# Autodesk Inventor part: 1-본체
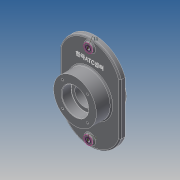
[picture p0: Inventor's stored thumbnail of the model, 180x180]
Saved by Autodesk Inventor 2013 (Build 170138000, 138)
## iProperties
Created: 2015-02
Part Number: 1-본체
Material: 일반
Document SubType Name: Modeling
Designer: kb543-18
Density: 1 g/cm^3
Mass: 603.771 g
Surface Area: 900.498 cm^2
Volume: 603.771 cm^3
Author: kb543-18
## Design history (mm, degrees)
sketch "스케치1"
  geometry: L1 (-70, -60)-(-70, 60); L2 (70, 60)-(70, -60); L3 (70, -60)-(-70, 60); L4 (-70, -60)-(70, 60); L5 (-70, 60)-(70, 60); L6 (-70, -60)-(70, -60); A1 r 74 centre (0, 36) between (70, 60) and (-70, 60); A2 r 74 centre (0, -36) between (-70, -60) and (70, -60); 2 further points
  constraints: 12 end point, 4 point on circle, 2 centre point, 2 parallel, 1 coincident, 1 equal radius, 1 horizontal, 1 midpoint, 1 perpendicular
  dimensions: "d0" = 120 distance of L2.start L2.end; "d2" = 140 distance of L1.end L2.start; "d3" = 50 distance edge to line of A1 L5
extrude "돌출1" new body sketch "스케치1" distance "d5" = 12; taper "d6" = 0 deg
node "작업 평면2"
sketch "스케치3"
  geometry: C1 r 50 at (0, 0); C2 r 31 at (0, 0); C3 r 22.5 at (0, 0); 1 further point
  constraints: 3 centre point, 3 coincident
  dimensions: "d8" = 100 diameter of C1; "d10" = 62 diameter of C2; "d11" = 45 diameter of C3
extrude "돌출2" join sketch "스케치3" distance "d12" = 70; taper "d13" = 0 deg
extrude "돌출3" cut sketch "스케치3" distance "d14" = 22; taper "d15" = 0 deg
extrude "돌출4" cut sketch "스케치3" distance "d16" = 70; taper "d17" = 0 deg
sketch "스케치4"
  geometry: C1 r 22.5 at (0, 0) reference; C2 r 50 at (0, 0) reference; C3 r 31 at (0, 0)
  constraints: 1 centre point, 1 coincident
  dimensions: "d18" = 62 diameter of C3
extrude "돌출5" cut sketch "스케치4" distance "d20" = 22; taper "d21" = 0 deg
sketch "스케치5"
  geometry: L1 (-70, -60)-(-70, 60) reference; L2 (70, 60)-(70, -60) reference; L3 (-53, 56.976)-(-53, -56.976); L4 (53, -56.976)-(53, 56.976); C1 r 10 at (0, 93); C2 r 10 at (0, -93); C3 r 5.5 at (0, -93); C4 r 10 at (-53, 56.976); C5 r 10 at (53, 56.976); C6 r 10 at (53, -56.976); C7 r 10 at (-53, -56.976); A1 r 74 centre (0, -36) between (-70, -60) and (70, -60) reference; A2 r 74 centre (0, 36) between (70, 60) and (-70, 60) reference; A3 r 57 centre (0, -36) between (-53, -56.976) and (53, -56.976); A4 r 57 centre (0, 36) between (53, 56.976) and (-53, 56.976); 2 further points
  constraints: 9 centre point, 7 point on circle, 5 equal radius, 4 end point, 3 coincident, 3 point on line, 2 horizontal alignment, 3 other
  dimensions: "d22" = 17 distance between parallel lines of L2 L4; "d23" = 20 diameter of C1; "d30" = 11 diameter of C3; "d65" = 36.02382 vertical distance of C6.centre point (0, -93) (derived); "d66" = 36.02382 vertical distance of C1.centre C4.centre (derived)
extrude "돌출6" join sketch "스케치5" distance "d24" = 5; taper "d25" = 0 deg
sketch "스케치6"
  geometry: C1 r 10 at (0, 0) reference; C2 r 5.5 at (0, 0); C3 r 10 at (0, -186) reference; C4 r 5.5 at (0, -186); 1 further point
  constraints: 2 centre point, 2 coincident
  dimensions: "d26" = 11 diameter of C2; "d31" = 11 diameter of C4
  node "투영된 루프1"
extrude "돌출7" cut sketch "스케치6" stored distance "d28" = 5; taper "d29" = 0 deg
sketch "스케치7"
  geometry: L1 (0, 0)-(0, 41); L2 (0, 0)-(28.991, 28.991); C1 r 50 at (0, 0) reference; C2 r 50 at (0, 0) reference; A1 r 41 centre (0, 0) between (28.991, 28.991) and (0, 41); 1 further point
  constraints: 4 end point, 2 coincident, 2 point on circle, 1 centre point, 1 vertical
  dimensions: "d32" = 45 deg angle of L1 L2; "d33" = 82 diameter of A1
node "작업 평면3"
sketch "스케치8"
  geometry: C1 r 50 at (0, 0) reference; 1 further point
  constraints: 1 vertical alignment, 1 other
  dimensions: "d44" = 65 distance of point (0, 65) C1.centre
feature "엠보싱1" sketch "스케치8" dims "d0" = 120, "d2" = 140, "d3" = 50, "d45" = 1, "d46" = 0
fillet "모깎기1" dims "d47" = 3
chamfer "모따기1" distance "d48" = 1; stored, may be unused: second distance "d49" = 2, angle "d50" = 45 deg
fillet "모깎기2" dims "d51" = 0.3
hole "구멍2" sketch "스케치7" diameter "d52" = 4.917; stored, may be unused: countersink angle "d56" = 90 deg, drill point angle "d58" = 118 deg; dims "d53" = 10, "d54" = 4, "d55" = 2, "d57" = 13
node "작업 평면4"
node "솔리드1"
pattern_circular "원형 패턴2" dims angle "d60" = 360 deg
mirror "대칭2"
other parameters: "d7" = 23
